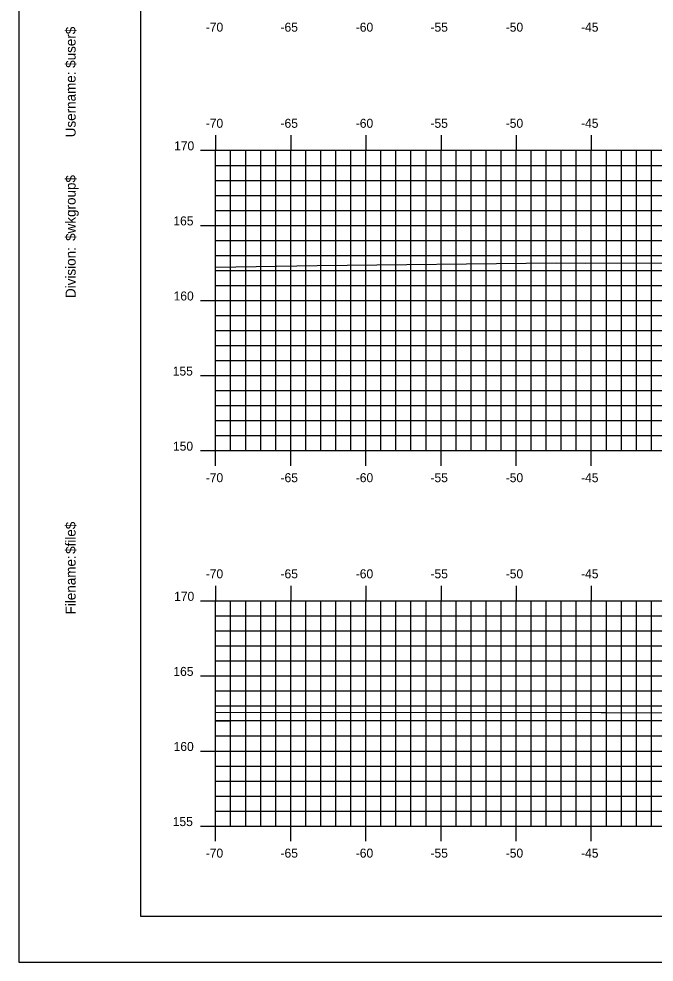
# Model space of a CAD drawing. Extents: x 1142976 to 1143146, y 608981 to 609091.
# Drawn here: x 1142976.5 to 1143018.7, y 608981.3 to 609044.1 of the extents above; entities that cross this region are included whole.
import ezdxf

# ---------------------------------------------------------------- set-up
doc = ezdxf.new("R2010")
doc.units = 0
for name, color, linetype in [('BORDER', 7, 'Continuous'), ('H_V ANNOTATION', 7, 'Continuous'), ('MAJOR', 7, 'Continuous'), ('MINOR', 7, 'Continuous'), ('PLOT BOUNDARY', 7, 'Continuous'), ('S_Roadway_Centerline', 7, 'Continuous')]:
    doc.layers.add(name, color=color, linetype=linetype)

msp = doc.modelspace()

# ---------------------------------------------------------------- linework, layer by layer
at = {"layer": 'BORDER'}
msp.add_lwpolyline([(1142984.567, 608984.335), (1143144.567, 608984.335), (1143144.567, 609089.335), (1142984.567, 609089.335)], close=True, dxfattribs=at)
at = {"layer": 'MAJOR'}
for p, q in [((1142989.567, 609036.337), (1142989.567, 609035.335)), ((1142994.567, 609036.337), (1142994.567, 609035.335)), ((1142999.567, 609036.337), (1142999.567, 609035.335)), ((1143004.567, 609036.337), (1143004.567, 609035.335)), ((1143009.567, 609036.337), (1143009.567, 609035.335)), ((1143014.567, 609036.337), (1143014.567, 609035.335)), ((1142988.565, 609035.335), (1142989.567, 609035.335)), ((1142989.567, 609035.335), (1143129.567, 609035.335)), ((1142989.567, 609015.335), (1142989.567, 609035.335)), ((1142989.567, 609015.335), (1142989.567, 609035.335)), ((1142989.567, 609035.335), (1143129.567, 609035.335)), ((1142994.567, 609015.335), (1142994.567, 609035.335)), ((1142999.567, 609015.335), (1142999.567, 609035.335)), ((1143004.567, 609015.335), (1143004.567, 609035.335)), ((1143009.567, 609015.335), (1143009.567, 609035.335)), ((1143014.567, 609015.335), (1143014.567, 609035.335)), ((1142988.565, 609030.335), (1142989.567, 609030.335)), ((1142989.567, 609030.335), (1143129.567, 609030.335)), ((1142988.565, 609025.335), (1142989.567, 609025.335)), ((1142989.567, 609025.335), (1143129.567, 609025.335)), ((1142988.565, 609020.335), (1142989.567, 609020.335)), ((1142989.567, 609020.335), (1143129.567, 609020.335)), ((1142988.565, 609015.335), (1142989.567, 609015.335)), ((1142989.567, 609015.335), (1143129.567, 609015.335)), ((1142989.567, 609015.335), (1143129.567, 609015.335)), ((1142989.567, 609014.333), (1142989.567, 609015.335)), ((1142994.567, 609014.333), (1142994.567, 609015.335)), ((1142999.567, 609014.333), (1142999.567, 609015.335)), ((1143004.567, 609014.333), (1143004.567, 609015.335)), ((1143009.567, 609014.333), (1143009.567, 609015.335)), ((1143014.567, 609014.333), (1143014.567, 609015.335)), ((1142989.567, 609006.337), (1142989.567, 609005.335)), ((1142994.567, 609006.337), (1142994.567, 609005.335)), ((1142999.567, 609006.337), (1142999.567, 609005.335)), ((1143004.567, 609006.337), (1143004.567, 609005.335)), ((1143009.567, 609006.337), (1143009.567, 609005.335)), ((1143014.567, 609006.337), (1143014.567, 609005.335)), ((1142988.565, 609005.335), (1142989.567, 609005.335)), ((1142989.567, 609005.335), (1143129.567, 609005.335)), ((1142989.567, 608990.335), (1142989.567, 609005.335)), ((1142989.567, 608990.335), (1142989.567, 609005.335)), ((1142989.567, 609005.335), (1143129.567, 609005.335)), ((1142994.567, 608990.335), (1142994.567, 609005.335)), ((1142999.567, 608990.335), (1142999.567, 609005.335)), ((1143004.567, 608990.335), (1143004.567, 609005.335)), ((1143009.567, 608990.335), (1143009.567, 609005.335)), ((1143014.567, 608990.335), (1143014.567, 609005.335)), ((1142988.565, 609000.335), (1142989.567, 609000.335)), ((1142989.567, 609000.335), (1143129.567, 609000.335)), ((1142988.565, 608995.335), (1142989.567, 608995.335)), ((1142989.567, 608995.335), (1143129.567, 608995.335)), ((1142988.565, 608990.335), (1142989.567, 608990.335)), ((1142989.567, 608990.335), (1143129.567, 608990.335)), ((1142989.567, 608990.335), (1143129.567, 608990.335)), ((1142989.567, 608989.333), (1142989.567, 608990.335)), ((1142994.567, 608989.333), (1142994.567, 608990.335)), ((1142999.567, 608989.333), (1142999.567, 608990.335)), ((1143004.567, 608989.333), (1143004.567, 608990.335)), ((1143009.567, 608989.333), (1143009.567, 608990.335)), ((1143014.567, 608989.333), (1143014.567, 608990.335))]:
    msp.add_line(p, q, dxfattribs=at)
at = {"layer": 'MINOR'}
for p, q in [((1142990.567, 609015.335), (1142990.567, 609035.335)), ((1142991.567, 609015.335), (1142991.567, 609035.335)), ((1142992.567, 609015.335), (1142992.567, 609035.335)), ((1142993.567, 609015.335), (1142993.567, 609035.335)), ((1142995.567, 609015.335), (1142995.567, 609035.335)), ((1142996.567, 609015.335), (1142996.567, 609035.335)), ((1142997.567, 609015.335), (1142997.567, 609035.335)), ((1142998.567, 609015.335), (1142998.567, 609035.335)), ((1143000.567, 609015.335), (1143000.567, 609035.335)), ((1143001.567, 609015.335), (1143001.567, 609035.335)), ((1143002.567, 609015.335), (1143002.567, 609035.335)), ((1143003.567, 609015.335), (1143003.567, 609035.335)), ((1143005.567, 609015.335), (1143005.567, 609035.335)), ((1143006.567, 609015.335), (1143006.567, 609035.335)), ((1143007.567, 609015.335), (1143007.567, 609035.335)), ((1143008.567, 609015.335), (1143008.567, 609035.335)), ((1143010.567, 609015.335), (1143010.567, 609035.335)), ((1143011.567, 609015.335), (1143011.567, 609035.335)), ((1143012.567, 609015.335), (1143012.567, 609035.335)), ((1143013.567, 609015.335), (1143013.567, 609035.335)), ((1143015.567, 609015.335), (1143015.567, 609035.335)), ((1143016.567, 609015.335), (1143016.567, 609035.335)), ((1143017.567, 609015.335), (1143017.567, 609035.335)), ((1143018.567, 609015.335), (1143018.567, 609035.335)), ((1142989.567, 609034.335), (1143129.567, 609034.335)), ((1142989.567, 609034.335), (1142990.569, 609034.335)), ((1142989.567, 609033.335), (1143129.567, 609033.335)), ((1142989.567, 609033.335), (1142990.569, 609033.335)), ((1142989.567, 609032.335), (1143129.567, 609032.335)), ((1142989.567, 609032.335), (1142990.569, 609032.335)), ((1142989.567, 609031.335), (1143129.567, 609031.335)), ((1142989.567, 609031.335), (1142990.569, 609031.335)), ((1142989.567, 609029.335), (1143129.567, 609029.335)), ((1142989.567, 609029.335), (1142990.569, 609029.335)), ((1142989.567, 609028.335), (1143129.567, 609028.335)), ((1142989.567, 609028.335), (1142990.569, 609028.335)), ((1142989.567, 609027.335), (1143129.567, 609027.335)), ((1142989.567, 609027.335), (1142990.569, 609027.335)), ((1142989.567, 609026.335), (1143129.567, 609026.335)), ((1142989.567, 609026.335), (1142990.569, 609026.335)), ((1142989.567, 609024.335), (1143129.567, 609024.335)), ((1142989.567, 609024.335), (1142990.569, 609024.335)), ((1142989.567, 609023.335), (1143129.567, 609023.335)), ((1142989.567, 609023.335), (1142990.569, 609023.335)), ((1142989.567, 609022.335), (1143129.567, 609022.335)), ((1142989.567, 609022.335), (1142990.569, 609022.335)), ((1142989.567, 609021.335), (1143129.567, 609021.335)), ((1142989.567, 609021.335), (1142990.569, 609021.335)), ((1142989.567, 609019.335), (1143129.567, 609019.335)), ((1142989.567, 609019.335), (1142990.569, 609019.335)), ((1142989.567, 609018.335), (1143129.567, 609018.335)), ((1142989.567, 609018.335), (1142990.569, 609018.335)), ((1142989.567, 609017.335), (1143129.567, 609017.335)), ((1142989.567, 609017.335), (1142990.569, 609017.335)), ((1142989.567, 609016.335), (1143129.567, 609016.335)), ((1142989.567, 609016.335), (1142990.569, 609016.335)), ((1142990.567, 608990.335), (1142990.567, 609005.335)), ((1142991.567, 608990.335), (1142991.567, 609005.335)), ((1142992.567, 608990.335), (1142992.567, 609005.335)), ((1142993.567, 608990.335), (1142993.567, 609005.335)), ((1142995.567, 608990.335), (1142995.567, 609005.335)), ((1142996.567, 608990.335), (1142996.567, 609005.335)), ((1142997.567, 608990.335), (1142997.567, 609005.335)), ((1142998.567, 608990.335), (1142998.567, 609005.335)), ((1143000.567, 608990.335), (1143000.567, 609005.335)), ((1143001.567, 608990.335), (1143001.567, 609005.335)), ((1143002.567, 608990.335), (1143002.567, 609005.335)), ((1143003.567, 608990.335), (1143003.567, 609005.335)), ((1143005.567, 608990.335), (1143005.567, 609005.335)), ((1143006.567, 608990.335), (1143006.567, 609005.335)), ((1143007.567, 608990.335), (1143007.567, 609005.335)), ((1143008.567, 608990.335), (1143008.567, 609005.335)), ((1143010.567, 608990.335), (1143010.567, 609005.335)), ((1143011.567, 608990.335), (1143011.567, 609005.335)), ((1143012.567, 608990.335), (1143012.567, 609005.335)), ((1143013.567, 608990.335), (1143013.567, 609005.335)), ((1143015.567, 608990.335), (1143015.567, 609005.335)), ((1143016.567, 608990.335), (1143016.567, 609005.335)), ((1143017.567, 608990.335), (1143017.567, 609005.335)), ((1143018.567, 608990.335), (1143018.567, 609005.335)), ((1142989.567, 609004.335), (1143129.567, 609004.335)), ((1142989.567, 609004.335), (1142990.569, 609004.335)), ((1142989.567, 609003.335), (1143129.567, 609003.335)), ((1142989.567, 609003.335), (1142990.569, 609003.335)), ((1142989.567, 609002.335), (1143129.567, 609002.335)), ((1142989.567, 609002.335), (1142990.569, 609002.335)), ((1142989.567, 609001.335), (1143129.567, 609001.335)), ((1142989.567, 609001.335), (1142990.569, 609001.335)), ((1142989.567, 608999.335), (1143129.567, 608999.335)), ((1142989.567, 608999.335), (1142990.569, 608999.335)), ((1142989.567, 608998.335), (1143129.567, 608998.335)), ((1142989.567, 608998.335), (1142990.569, 608998.335)), ((1143129.567, 608997.335), (1142989.567, 608997.335)), ((1142989.567, 608997.335), (1142990.569, 608997.335)), ((1142989.567, 608996.335), (1143129.567, 608996.335)), ((1142989.567, 608996.335), (1142990.569, 608996.335)), ((1142989.567, 608994.335), (1143129.567, 608994.335)), ((1142989.567, 608994.335), (1142990.569, 608994.335)), ((1142989.567, 608993.335), (1143129.567, 608993.335)), ((1142989.567, 608993.335), (1142990.569, 608993.335)), ((1142989.567, 608992.335), (1143129.567, 608992.335)), ((1142989.567, 608992.335), (1142990.569, 608992.335)), ((1142989.567, 608991.335), (1143129.567, 608991.335)), ((1142989.567, 608991.335), (1142990.569, 608991.335))]:
    msp.add_line(p, q, dxfattribs=at)
at = {"layer": 'PLOT BOUNDARY'}
msp.add_lwpolyline([(1142976.473, 608981.276), (1143146.473, 608981.276), (1143146.473, 609091.276), (1142976.473, 609091.276)], close=True, dxfattribs=at)
at = {"layer": 'S_Roadway_Centerline'}
for points in [[(1142989.567, 609027.545), (1142996.316, 609027.669), (1143012.235, 609027.85), (1143014.156, 609027.829), (1143032.215, 609027.857), (1143036.466, 609027.056), (1143037.644, 609026.918), (1143039.915, 609027.744), (1143040.829, 609027.969), (1143043.332, 609028.06), (1143044.384, 609028.129), (1143052.209, 609028.413), (1143055.628, 609028.504), (1143058.799, 609028.519), (1143067.081, 609028.581), (1143068.236, 609028.458), (1143070.515, 609028.236), (1143071.722, 609027.944), (1143074.732, 609027.136), (1143077.419, 609027.321)], [(1142989.567, 608997.913), (1143015.23, 608997.899), (1143015.369, 608997.901), (1143015.581, 608997.899), (1143035.144, 608997.818), (1143036.675, 608997.612), (1143039.235, 608997.313), (1143040.24, 608997.57), (1143042.363, 608998.094), (1143044.738, 608998.247), (1143045.936, 608998.359), (1143049.94, 608998.493), (1143057.403, 608998.694), (1143064.179, 608998.728), (1143068.256, 608998.668), (1143069.663, 608998.56), (1143071.984, 608998.313), (1143074.42, 608997.723), (1143075.581, 608997.422), (1143077.949, 608997.561), (1143080.787, 608997.747), (1143089.847, 608997.631), (1143111.617, 608997.433), (1143129.567, 608997.446)]]:
    msp.add_lwpolyline(points, dxfattribs=at)

# ---------------------------------------------------------------- texts
at = {"layer": 'BORDER'}
for s, p in [('$user$', (1142980.252, 609040.827)), ('Username:', (1142980.252, 609036.203)), ('$wkgroup$', (1142980.252, 609029.305)), ('Division:', (1142980.252, 609025.501)), ('$file$', (1142980.252, 609008.461)), ('Filename:', (1142980.252, 609004.433))]:
    msp.add_text(s, height=0.6696, rotation=90, dxfattribs=at).set_placement(p)
at = {"layer": 'H_V ANNOTATION'}
for s, p in [('-70', (1142988.908, 609043.235)), ('-65', (1142993.884, 609043.235)), ('-60', (1142998.892, 609043.235)), ('-55', (1143003.863, 609043.235)), ('-50', (1143008.871, 609043.235)), ('-45', (1143013.884, 609043.235)), ('-70', (1142988.908, 609036.835)), ('-65', (1142993.884, 609036.835)), ('-60', (1142998.892, 609036.835)), ('-55', (1143003.863, 609036.835)), ('-50', (1143008.871, 609036.835)), ('-45', (1143013.884, 609036.835)), ('170', (1142986.803, 609035.335)), ('165', (1142986.755, 609030.335)), ('160', (1142986.771, 609025.335)), ('155', (1142986.712, 609020.335)), ('150', (1142986.728, 609015.335)), ('-70', (1142988.908, 609013.235)), ('-65', (1142993.884, 609013.235)), ('-60', (1142998.892, 609013.235)), ('-55', (1143003.863, 609013.235)), ('-50', (1143008.871, 609013.235)), ('-45', (1143013.884, 609013.235)), ('-70', (1142988.908, 609006.835)), ('-65', (1142993.884, 609006.835)), ('-60', (1142998.892, 609006.835)), ('-55', (1143003.863, 609006.835)), ('-50', (1143008.871, 609006.835)), ('-45', (1143013.884, 609006.835)), ('170', (1142986.803, 609005.335)), ('165', (1142986.755, 609000.335)), ('160', (1142986.771, 608995.335)), ('155', (1142986.712, 608990.335)), ('-70', (1142988.908, 608988.235)), ('-65', (1142993.884, 608988.235)), ('-60', (1142998.892, 608988.235)), ('-55', (1143003.863, 608988.235)), ('-50', (1143008.871, 608988.235)), ('-45', (1143013.884, 608988.235))]:
    msp.add_text(s, height=0.6, dxfattribs=at).set_placement(p)
at = {"layer": 'MAJOR'}
for p in [(1142989.562, 609015.335), (1142989.562, 608990.335)]:
    msp.add_text('-', height=0.006, dxfattribs=at).set_placement(p)

doc.saveas('drawing.dxf')
